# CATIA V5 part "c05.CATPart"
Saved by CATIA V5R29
Part number: c05
Source: Unknown
Bounding box of the stored display mesh (mm): x 16.662 to 134.073, y -101 to 75, z 102.292 to 225.053
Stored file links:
  C:\가치같이\SmartFactory_BoxErectorConveyor\Boxing(under)\c05.CATPart
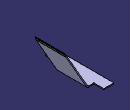
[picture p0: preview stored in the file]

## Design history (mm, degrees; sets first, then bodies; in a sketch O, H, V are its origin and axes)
Body1 (main body)
  Solid1 "PartBody": solid without history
